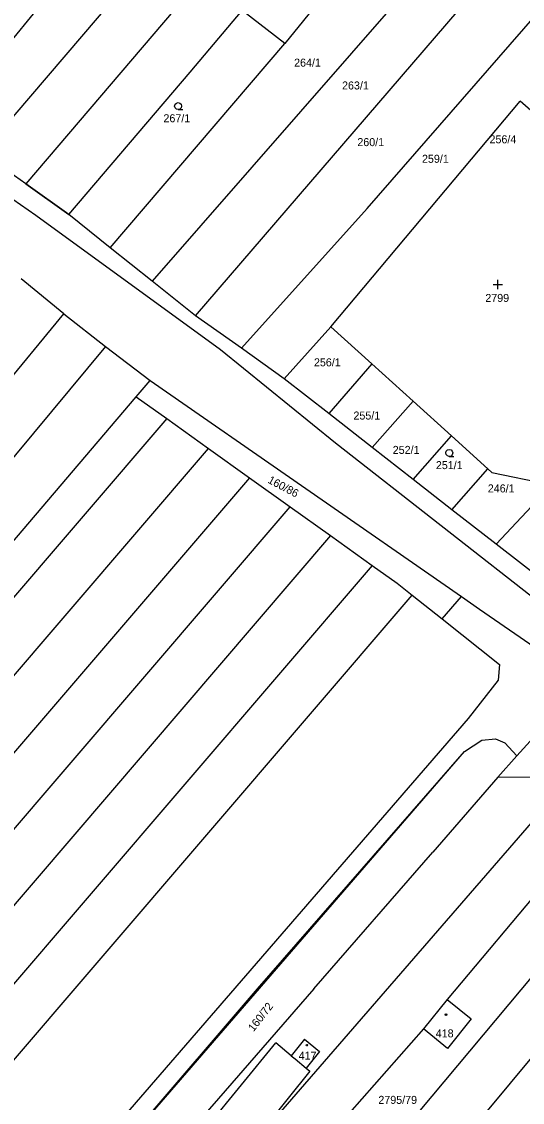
# Model space of a CAD drawing. Extents: x -580630 to -576196, y -1189024 to -1183567.
# Drawn here: x -579073.9 to -578967.5, y -1185934.4 to -1185704.7 of the extents above; entities that cross this region are included whole.
import ezdxf

# ---------------------------------------------------------------- set-up
doc = ezdxf.new("R2010")
doc.units = 0
for name, color, linetype in [('Vrstva 1', 7, 'Continuous'), ('Vrstva 16', 7, 'Continuous'), ('Vrstva 18', 7, 'Continuous'), ('Vrstva 19', 7, 'Continuous'), ('Vrstva 25', 7, 'Continuous'), ('Vrstva 6', 7, 'Continuous'), ('Vrstva 63', 7, 'Continuous')]:
    doc.layers.add(name, color=color, linetype=linetype)

msp = doc.modelspace()

# ---------------------------------------------------------------- linework, layer by layer
at = {"layer": 'Vrstva 1'}
for p, q in [((-579082.26, -1185732.61), (-579044.89, -1185688.85)), ((-578984.38, -1185689.13), (-579046.18, -1185759.89)), ((-579002.16, -1185689.77), (-579018.01, -1185709.37)), ((-579061.52, -1185690.84), (-579090.91, -1185726.96)), ((-579036.95, -1185767.23), (-578974.58, -1185694.7)), ((-579039.03, -1185699.35), (-579072.99, -1185739.21)), ((-579038.09, -1185715.47), (-579027.07, -1185702.33)), ((-579018.01, -1185709.37), (-579027.07, -1185702.33)), ((-579000.48, -1185744.42), (-578964.78, -1185703.46)), ((-579055.08, -1185752.81), (-579018.01, -1185709.37)), ((-579063.86, -1185745.7), (-579038.09, -1185715.47)), ((-579008.19, -1185769.58), (-578967.96, -1185721.6)), ((-578965.75, -1185723.59), (-578967.96, -1185721.6)), ((-579072.99, -1185739.21), (-579082.26, -1185732.61)), ((-579086.66, -1185734.87), (-579070.88, -1185745.81)), ((-579072.99, -1185739.21), (-579063.86, -1185745.7)), ((-579027.17, -1185774.08), (-579000.48, -1185744.42)), ((-579070.88, -1185745.81), (-579031.67, -1185774.41)), ((-579055.08, -1185752.81), (-579063.86, -1185745.7)), ((-579046.18, -1185759.89), (-579055.08, -1185752.81)), ((-579064.92, -1185766.8), (-579073.99, -1185759.36)), ((-579036.95, -1185767.23), (-579046.18, -1185759.89)), ((-579064.92, -1185766.8), (-579056.06, -1185773.75)), ((-579027.17, -1185774.08), (-579036.95, -1185767.23)), ((-579018.1, -1185780.64), (-579008.19, -1185769.58)), ((-578999.49, -1185777.45), (-579008.19, -1185769.58)), ((-579056.06, -1185773.75), (-579046.61, -1185781)), ((-579031.67, -1185774.41), (-579007.22, -1185794.23)), ((-579018.1, -1185780.64), (-579027.17, -1185774.08)), ((-578999.49, -1185777.45), (-579008.66, -1185788)), ((-578990.72, -1185785.38), (-578999.49, -1185777.45)), ((-579049.55, -1185784.45), (-579046.61, -1185781)), ((-579046.61, -1185781), (-578980.47, -1185826.86)), ((-579008.66, -1185788), (-579018.1, -1185780.64)), ((-579080.09, -1185820.33), (-579049.55, -1185784.45)), ((-579049.55, -1185784.45), (-579043.07, -1185789.08)), ((-578999.45, -1185795.19), (-578990.72, -1185785.38)), ((-578982.58, -1185792.74), (-578990.72, -1185785.38)), ((-578999.45, -1185795.19), (-579008.66, -1185788)), ((-579043.07, -1185789.08), (-579516.28, -1186341.47)), ((-579043.07, -1185789.08), (-579034.2, -1185795.41)), ((-578990.73, -1185802), (-578982.58, -1185792.74)), ((-578974.85, -1185799.73), (-578982.58, -1185792.74)), ((-579560.3, -1186409.54), (-579034.2, -1185795.41)), ((-579034.2, -1185795.41), (-579025.51, -1185801.62)), ((-579007.22, -1185794.23), (-578958.14, -1185832.65)), ((-578990.73, -1185802), (-578999.45, -1185795.19)), ((-578982.5, -1185808.42), (-578974.85, -1185799.73)), ((-578973.99, -1185800.51), (-578974.85, -1185799.73)), ((-579025.51, -1185801.62), (-579550.65, -1186414.64)), ((-579025.51, -1185801.62), (-579016.85, -1185807.81)), ((-578982.5, -1185808.42), (-578990.73, -1185802)), ((-578973.99, -1185800.51), (-578961.26, -1185803.13)), ((-578973.12, -1185815.74), (-578961.26, -1185803.13)), ((-579541.04, -1186419.71), (-579016.85, -1185807.81)), ((-579016.85, -1185807.81), (-579008.27, -1185813.94)), ((-578973.12, -1185815.74), (-578982.5, -1185808.42)), ((-579008.27, -1185813.94), (-579531.52, -1186424.74)), ((-579008.27, -1185813.94), (-578999.43, -1185820.25)), ((-578955.79, -1185829.25), (-578973.12, -1185815.74)), ((-578999.43, -1185820.25), (-579414.73, -1186305.04)), ((-578999.43, -1185820.25), (-578994.09, -1185824.07)), ((-578994.09, -1185824.07), (-578990.93, -1185826.58)), ((-579398.1, -1186301.88), (-578990.93, -1185826.58)), ((-578990.93, -1185826.58), (-578984.57, -1185831.64)), ((-578984.57, -1185831.64), (-578980.47, -1185826.86)), ((-578980.47, -1185826.86), (-578976.62, -1185829.53)), ((-578976.62, -1185829.53), (-578962.79, -1185839.1)), ((-578984.57, -1185831.64), (-578972.39, -1185841.32)), ((-578972.39, -1185841.32), (-578972.64, -1185844.66)), ((-578972.64, -1185844.66), (-578979.05, -1185852.8)), ((-578979.05, -1185852.8), (-579170.73, -1186074.45)), ((-578960.86, -1185852.01), (-578968.7, -1185860.75)), ((-578979.81, -1185859.79), (-578976.11, -1185857.4)), ((-578976.11, -1185857.4), (-578973.2, -1185857.08)), ((-578973.2, -1185857.08), (-578971.23, -1185857.98)), ((-578971.23, -1185857.98), (-578968.7, -1185860.75)), ((-579167.73, -1186077.09), (-578979.81, -1185859.79)), ((-578968.7, -1185860.75), (-578972.77, -1185865.29)), ((-578972.77, -1185865.29), (-578986.56, -1185881.21)), ((-578957.26, -1185865.31), (-578972.77, -1185865.29)), ((-579011.85, -1185910.24), (-578986.56, -1185881.21)), ((-579011.85, -1185910.24), (-579032.1, -1185933.51)), ((-578983.5, -1185912.52), (-578988.52, -1185918.71)), ((-578983.5, -1185912.52), (-578978.42, -1185916.61)), ((-578978.42, -1185916.61), (-578983.42, -1185922.95)), ((-578983.42, -1185922.95), (-578988.52, -1185918.71)), ((-579037.07, -1185942.75), (-579019.92, -1185921.72)), ((-579016.63, -1185924.44), (-579019.92, -1185921.72)), ((-579013.78, -1185920.95), (-579016.63, -1185924.44)), ((-579013.78, -1185920.95), (-579010.59, -1185923.56)), ((-579010.59, -1185923.56), (-579013.43, -1185927.08)), ((-579016.63, -1185924.44), (-579015.78, -1185925.14)), ((-579015.78, -1185925.14), (-579013.43, -1185927.08)), ((-579012.69, -1185927.7), (-579029.6, -1185948.76)), ((-579013.43, -1185927.08), (-579012.69, -1185927.7)), ((-579032.1, -1185933.51), (-579069.79, -1185976.93))]:
    msp.add_line(p, q, dxfattribs=at)
at = {"layer": 'Vrstva 25'}
for p, q in [((-578973.72, -1185760.58), (-578971.72, -1185760.58)), ((-578972.72, -1185761.58), (-578972.72, -1185759.58))]:
    msp.add_line(p, q, dxfattribs=at)
for points in [[(-579040.64, -1185723.4), (-579041.02, -1185723.3), (-579041.29, -1185723.03), (-579041.39, -1185722.66), (-579041.29, -1185722.29), (-579041.02, -1185722.02), (-579040.65, -1185721.92), (-579040.28, -1185722.02), (-579040.01, -1185722.29), (-579039.91, -1185722.67), (-579040.01, -1185723.05), (-579040.28, -1185723.32), (-579040.66, -1185723.42), (-579039.66, -1185723.42)], [(-578983.04, -1185797.1), (-578983.42, -1185797), (-578983.69, -1185796.73), (-578983.79, -1185796.36), (-578983.69, -1185795.99), (-578983.42, -1185795.72), (-578983.05, -1185795.62), (-578982.68, -1185795.72), (-578982.41, -1185795.99), (-578982.31, -1185796.37), (-578982.41, -1185796.75), (-578982.68, -1185797.02), (-578983.06, -1185797.12), (-578982.06, -1185797.12)]]:
    msp.add_lwpolyline(points, dxfattribs=at)
for points in [[(-578983.67, -1185915.57), (-578983.58, -1185915.72), (-578983.67, -1185915.87), (-578983.85, -1185915.87), (-578983.94, -1185915.72), (-578983.85, -1185915.57)], [(-579013.2, -1185922.05), (-579013.11, -1185922.2), (-579013.2, -1185922.35), (-579013.38, -1185922.35), (-579013.47, -1185922.2), (-579013.38, -1185922.05)]]:
    msp.add_lwpolyline(points, close=True, dxfattribs=at)
at = {"layer": 'Vrstva 6'}
for p, q in [((-579256.06, -1185998.51), (-579064.92, -1185766.8)), ((-579056.06, -1185773.75), (-579100.1, -1185826.68)), ((-579029.6, -1185948.76), (-578957.26, -1185865.31)), ((-578947.8, -1185869.89), (-578983.5, -1185912.52)), ((-578993.65, -1185941.32), (-578939.33, -1185876.42)), ((-578985.03, -1185948.3), (-578930.81, -1185882.98)), ((-578988.52, -1185918.71), (-579026.98, -1185962.34))]:
    msp.add_line(p, q, dxfattribs=at)
at = {"layer": 'Vrstva 63'}
for p, q in [((-579072.99, -1185739.21), (-579082.26, -1185732.61)), ((-579063.86, -1185745.7), (-579072.99, -1185739.21)), ((-579055.08, -1185752.81), (-579063.86, -1185745.7)), ((-579046.18, -1185759.89), (-579055.08, -1185752.81)), ((-579036.95, -1185767.23), (-579046.18, -1185759.89)), ((-579027.17, -1185774.08), (-579036.95, -1185767.23)), ((-579018.1, -1185780.64), (-579027.17, -1185774.08)), ((-579008.66, -1185788), (-579018.1, -1185780.64)), ((-578999.45, -1185795.19), (-579008.66, -1185788)), ((-578990.73, -1185802), (-578999.45, -1185795.19)), ((-578982.5, -1185808.42), (-578990.73, -1185802)), ((-578973.12, -1185815.74), (-578982.5, -1185808.42)), ((-578955.79, -1185829.25), (-578973.12, -1185815.74)), ((-578968.7, -1185860.75), (-578960.86, -1185852.01)), ((-578979.81, -1185859.79), (-578976.11, -1185857.4)), ((-578976.11, -1185857.4), (-578973.2, -1185857.08)), ((-578973.2, -1185857.08), (-578971.23, -1185857.98)), ((-578971.23, -1185857.98), (-578968.7, -1185860.75)), ((-579023.767, -1185910.263), (-578979.81, -1185859.79)), ((-579073.77, -1185968.44), (-579023.767, -1185910.263))]:
    msp.add_line(p, q, dxfattribs=at)

# ---------------------------------------------------------------- texts
at = {"layer": 'Vrstva 16'}
msp.add_text('256/4', height=1.7, dxfattribs=at).set_placement((-578974.505, -1185730.57))
at = {"layer": 'Vrstva 18'}
for s, p in [('264/1', (-579016.009, -1185714.28)), ('263/1', (-579005.826, -1185719.13)), ('267/1', (-579043.759, -1185726.1)), ('260/1', (-579002.576, -1185731.17)), ('259/1', (-578988.846, -1185734.71)), ('2799', (-578975.397, -1185764.28)), ('256/1', (-579011.796, -1185777.96)), ('255/1', (-579003.403, -1185789.27)), ('252/1', (-578995.059, -1185796.57)), ('251/1', (-578985.898, -1185799.8)), ('246/1', (-578974.869, -1185804.75)), ('2795/79', (-578998.112, -1185934.68))]:
    msp.add_text(s, height=1.7, dxfattribs=at).set_placement(p)
for s, rotation, p in [('160/86', 331.97175, (-579021.749, -1185802.621)), ('160/72', 51.96727, (-579024.623, -1185919.46))]:
    msp.add_text(s, height=1.7, rotation=rotation, dxfattribs=at).set_placement(p)
at = {"layer": 'Vrstva 19'}
for s, p in [('418', (-578985.926, -1185920.55)), ('417', (-579015.046, -1185925.29))]:
    msp.add_text(s, height=1.7, dxfattribs=at).set_placement(p)

doc.saveas('drawing.dxf')
